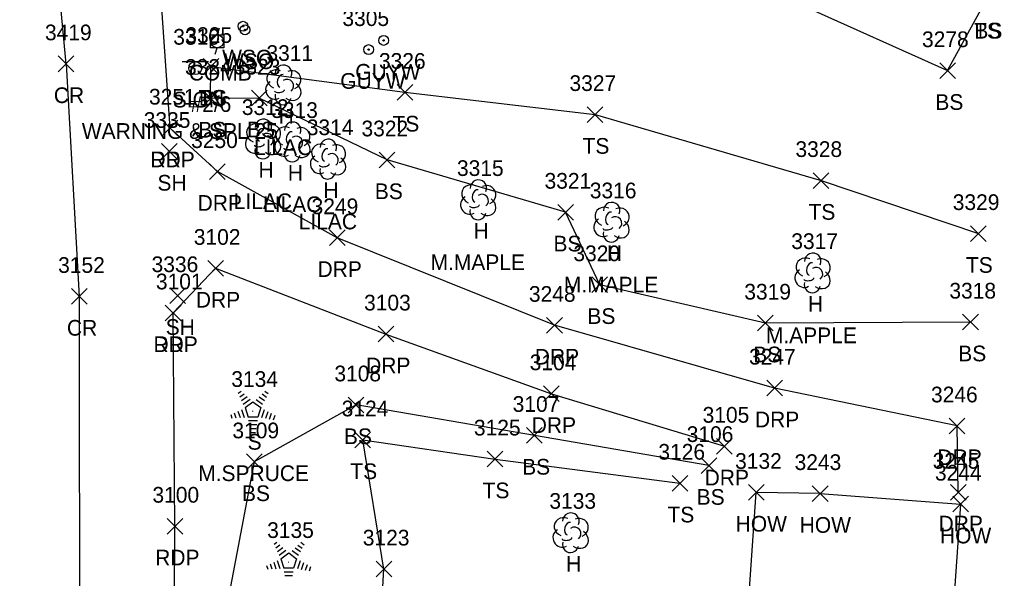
# Model space of a CAD drawing. Extents: x 1609623 to 1616187, y 756677 to 762826.
# Drawn here: x 1610609.3 to 1610734.4, y 762411.9 to 762483.1 of the extents above; entities that cross this region are included whole.
import ezdxf

# ---------------------------------------------------------------- set-up
doc = ezdxf.new("R2010")
doc.units = 0
for name, color, linetype in [('L_A', 7, 'Continuous'), ('L_C', 7, 'Continuous'), ('L_I', 7, 'Continuous'), ('L_TIC', 7, 'Continuous'), ('LBC', 7, 'Continuous'), ('LELB', 7, 'Continuous'), ('LTC', 7, 'Continuous'), ('LTD', 7, 'Continuous'), ('P_A', 7, 'Continuous'), ('P_I', 7, 'Continuous'), ('P_TIC', 7, 'Continuous'), ('PET', 7, 'Continuous'), ('PRC', 7, 'Continuous'), ('R_A', 7, 'Continuous'), ('R_I', 7, 'Continuous'), ('R_TIC', 7, 'Continuous'), ('RDP', 7, 'Continuous'), ('S_A', 7, 'Continuous'), ('S_C', 7, 'Continuous'), ('S_I', 7, 'Continuous'), ('SSGN', 7, 'Continuous'), ('U_A', 7, 'Continuous'), ('U_C', 7, 'Continuous'), ('U_I', 7, 'Continuous'), ('UP', 7, 'Continuous'), ('UPGW', 7, 'Continuous'), ('UWV', 7, 'Continuous')]:
    doc.layers.add(name, color=color, linetype=linetype)

msp = doc.modelspace()

# ---------------------------------------------------------------- linework, layer by layer
at = {"layer": 'L_TIC'}
for points in [[(1610632.67, 762476.12), (1610634.67, 762478.12)], [(1610634.67, 762476.12), (1610632.67, 762478.12)], [(1610632.67, 762476.12), (1610634.67, 762478.12)], [(1610634.67, 762476.12), (1610632.67, 762478.12)], [(1610726.55, 762475.59), (1610728.55, 762477.59)], [(1610728.55, 762475.59), (1610726.55, 762477.59)], [(1610657.39, 762472.83), (1610659.39, 762474.83)], [(1610659.39, 762472.83), (1610657.39, 762474.83)], [(1610632.62, 762472.06), (1610634.62, 762474.06)], [(1610634.62, 762472.06), (1610632.62, 762474.06)], [(1610638.83, 762472.09), (1610640.83, 762474.09)], [(1610640.83, 762472.09), (1610638.83, 762474.09)], [(1610681.62, 762470), (1610683.62, 762472)], [(1610683.62, 762470), (1610681.62, 762472)], [(1610627.36, 762465.3), (1610629.36, 762467.3)], [(1610629.36, 762465.3), (1610627.36, 762467.3)], [(1610655.11, 762464.22), (1610657.11, 762466.22)], [(1610657.11, 762464.22), (1610655.11, 762466.22)], [(1610710.42, 762461.59), (1610712.42, 762463.59)], [(1610712.42, 762461.59), (1610710.42, 762463.59)], [(1610677.87, 762457.55), (1610679.87, 762459.55)], [(1610679.87, 762457.55), (1610677.87, 762459.55)], [(1610730.48, 762454.83), (1610732.48, 762456.83)], [(1610732.48, 762454.83), (1610730.48, 762456.83)], [(1610682.21, 762448.31), (1610684.21, 762450.31)], [(1610684.21, 762448.31), (1610682.21, 762450.31)], [(1610628.42, 762446.92), (1610630.42, 762448.92)], [(1610630.42, 762446.92), (1610628.42, 762448.92)], [(1610729.47, 762443.55), (1610731.47, 762445.55)], [(1610731.47, 762443.55), (1610729.47, 762445.55)], [(1610703.34, 762443.42), (1610705.34, 762445.42)], [(1610705.34, 762443.42), (1610703.34, 762445.42)], [(1610651.17, 762433), (1610653.17, 762435)], [(1610653.17, 762433), (1610651.17, 762435)], [(1610652.02, 762428.54), (1610654.02, 762430.54)], [(1610654.02, 762428.54), (1610652.02, 762430.54)], [(1610673.89, 762429.11), (1610675.89, 762431.11)], [(1610675.89, 762429.11), (1610673.89, 762431.11)], [(1610668.88, 762426.1), (1610670.88, 762428.1)], [(1610670.88, 762426.1), (1610668.88, 762428.1)], [(1610638.18, 762425.74), (1610640.18, 762427.74)], [(1610640.18, 762425.74), (1610638.18, 762427.74)], [(1610696.13, 762425.27), (1610698.13, 762427.27)], [(1610698.13, 762425.27), (1610696.13, 762427.27)], [(1610692.44, 762423.02), (1610694.44, 762425.02)], [(1610694.44, 762423.02), (1610692.44, 762425.02)], [(1610702.16, 762421.85), (1610704.16, 762423.85)], [(1610704.16, 762421.85), (1610702.16, 762423.85)], [(1610710.31, 762421.7), (1610712.31, 762423.7)], [(1610712.31, 762421.7), (1610710.31, 762423.7)], [(1610728.2, 762420.35), (1610730.2, 762422.35)], [(1610730.2, 762420.35), (1610728.2, 762422.35)], [(1610654.72, 762412.08), (1610656.72, 762414.08)], [(1610656.72, 762412.08), (1610654.72, 762414.08)]]:
    msp.add_lwpolyline(points, dxfattribs=at)
at = {"layer": 'LBC'}
for points in [[(1610726.11, 762376.75), (1610699.95, 762378.87), (1610701.66, 762401.3), (1610703.16, 762422.85)], [(1610711.31, 762422.7), (1610703.16, 762422.85)], [(1610711.31, 762422.7), (1610729.2, 762421.35)], [(1610729.2, 762421.35), (1610726.11, 762376.75)]]:
    msp.add_lwpolyline(points, dxfattribs=at)
at = {"layer": 'LELB'}
for points in [[(1610617.17, 762584.2), (1610624.48, 762566.64), (1610633.74, 762545.52), (1610644.17, 762527.74), (1610665.38, 762506.98), (1610690.4, 762493.29), (1610727.55, 762476.59), (1610732.52, 762485.68)], [(1610730.47, 762444.55), (1610704.34, 762444.42), (1610683.21, 762449.31), (1610678.87, 762458.55), (1610656.11, 762465.22), (1610639.83, 762473.09), (1610633.62, 762473.06), (1610633.67, 762477.12)], [(1610633.67, 762477.12), (1610658.39, 762473.83), (1610682.62, 762471), (1610711.42, 762462.59), (1610731.48, 762455.83)], [(1610697.13, 762426.27), (1610674.89, 762430.11), (1610652.17, 762434), (1610639.18, 762426.74), (1610634.28, 762401.02), (1610634.83, 762377.24), (1610647.78, 762368.68), (1610668.95, 762368.97), (1610685.96, 762365.63), (1610692.89, 762346.49), (1610722.2, 762344.28)], [(1610722.2, 762344.28), (1610724.11, 762366.05), (1610703.11, 762368.06), (1610688.81, 762373.62), (1610671.14, 762377.72), (1610655.71, 762382.19), (1610654.46, 762391.1), (1610655.72, 762413.08), (1610653.02, 762429.54), (1610669.88, 762427.1), (1610693.44, 762424.02)]]:
    msp.add_lwpolyline(points, dxfattribs=at)
at = {"layer": 'LTC'}
for p, q in [((1610637.15, 762435.5), (1610637.51, 762435.76)), ((1610640.55, 762435.74), (1610640.97, 762435.43)), ((1610637.36, 762435.03), (1610637.89, 762435.42)), ((1610637.57, 762434.57), (1610638.28, 762435.08)), ((1610637.78, 762434.1), (1610638.66, 762434.74)), ((1610638.01, 762433.65), (1610639.02, 762434.38)), ((1610639.02, 762434.38), (1610640.02, 762433.66)), ((1610639.44, 762434.69), (1610640.25, 762434.1)), ((1610639.81, 762435.04), (1610640.49, 762434.55)), ((1610640.18, 762435.39), (1610640.73, 762434.99)), ((1610637.1, 762433.21), (1610637.37, 762432.38)), ((1610637.55, 762433.43), (1610637.88, 762432.41)), ((1610638.01, 762433.65), (1610638.39, 762432.45)), ((1610640.02, 762433.66), (1610639.62, 762432.45)), ((1610640.45, 762433.38), (1610640.11, 762432.35)), ((1610640.9, 762433.13), (1610640.61, 762432.25)), ((1610636.19, 762432.78), (1610636.34, 762432.31)), ((1610636.64, 762432.99), (1610636.85, 762432.34)), ((1610639.62, 762432.45), (1610638.39, 762432.45)), ((1610639.59, 762431.95), (1610638.44, 762431.95)), ((1610641.34, 762432.88), (1610641.1, 762432.15)), ((1610641.79, 762432.63), (1610641.6, 762432.06)), ((1610639.5, 762431.45), (1610638.51, 762431.45)), ((1610639.42, 762430.95), (1610638.59, 762430.95)), ((1610639.33, 762430.45), (1610638.66, 762430.45)), ((1610641.72, 762416.25), (1610642.08, 762416.5)), ((1610641.93, 762415.78), (1610642.46, 762416.17)), ((1610642.14, 762415.32), (1610642.84, 762415.83)), ((1610644.38, 762415.79), (1610645.06, 762415.3)), ((1610644.75, 762416.14), (1610645.3, 762415.74)), ((1610645.12, 762416.49), (1610645.54, 762416.18)), ((1610642.35, 762414.85), (1610643.23, 762415.49)), ((1610642.57, 762414.39), (1610643.59, 762415.13)), ((1610642.57, 762414.39), (1610642.96, 762413.2)), ((1610643.59, 762415.13), (1610644.58, 762414.4)), ((1610644.01, 762415.44), (1610644.82, 762414.85)), ((1610644.58, 762414.4), (1610644.19, 762413.2)), ((1610640.75, 762413.53), (1610640.91, 762413.06)), ((1610641.21, 762413.74), (1610641.42, 762413.09)), ((1610641.66, 762413.96), (1610641.94, 762413.12)), ((1610642.12, 762414.18), (1610642.45, 762413.16)), ((1610644.19, 762413.2), (1610642.96, 762413.2)), ((1610645.02, 762414.13), (1610644.68, 762413.09)), ((1610645.46, 762413.88), (1610645.18, 762413)), ((1610645.91, 762413.63), (1610645.67, 762412.9)), ((1610646.35, 762413.38), (1610646.17, 762412.81)), ((1610644.15, 762412.7), (1610643.01, 762412.7)), ((1610644.07, 762412.2), (1610643.08, 762412.2))]:
    msp.add_line(p, q, dxfattribs=at)
at = {"layer": 'LTD'}
for p, q in [((1610642.87, 762474.83), (1610642.87, 762474.83)), ((1610642.87, 762474.83), (1610642.87, 762474.83)), ((1610640.29, 762467.94), (1610640.29, 762467.94)), ((1610640.29, 762467.94), (1610640.29, 762467.94)), ((1610644.03, 762467.56), (1610644.03, 762467.56)), ((1610644.03, 762467.56), (1610644.03, 762467.56)), ((1610648.57, 762465.37), (1610648.57, 762465.37)), ((1610648.57, 762465.37), (1610648.57, 762465.37)), ((1610667.71, 762460.17), (1610667.71, 762460.17)), ((1610667.71, 762460.17), (1610667.71, 762460.17)), ((1610684.7, 762457.32), (1610684.7, 762457.32)), ((1610684.7, 762457.32), (1610684.7, 762457.32)), ((1610710.32, 762450.86), (1610710.32, 762450.86)), ((1610710.32, 762450.86), (1610710.32, 762450.86)), ((1610679.5, 762417.76), (1610679.5, 762417.76)), ((1610679.5, 762417.76), (1610679.5, 762417.76))]:
    msp.add_line(p, q, dxfattribs=at)
for centre in [(1610642.92, 762476.26), (1610640.34, 762469.37), (1610644.08, 762469), (1610648.62, 762466.81), (1610667.76, 762461.61), (1610684.75, 762458.76), (1610710.37, 762452.29), (1610679.54, 762419.19)]:
    msp.add_arc(centre, 1.05, 335.5272, 180.9563, dxfattribs=at)
for centre, major_axis, ratio, start_param, end_param in [((1610642.08, 762475.5), (1.21, -0.51), 0.895232, 1.570796, 4.712389), ((1610642.66, 762475.29), (-0.208, -0.792), 0.645439, 3.141593, 6.283185), ((1610643.37, 762474.66), (-0.5, 0.667), 0.989748, 3.141593, 6.283185), ((1610643.91, 762475.41), (-1.14, -0.48), 0.949671, 1.570796, 4.712389), ((1610641.79, 762474.12), (0.58, -1.04), 0.959034, 3.141593, 6.283185), ((1610643.87, 762474), (-1.09, 0.79), 0.841452, 1.570796, 4.712389), ((1610642.87, 762473.33), (0.26, 1.06), 0.942809, 1.570796, 4.712389), ((1610642.41, 762474.08), (-0.625, -0.083), 0.423636, 0, 3.141593), ((1610639.5, 762468.6), (1.21, -0.51), 0.895232, 1.570796, 4.712389), ((1610641.33, 762468.52), (-1.14, -0.48), 0.949671, 1.570796, 4.712389), ((1610643.24, 762468.23), (1.21, -0.51), 0.895232, 1.570796, 4.712389), ((1610645.07, 762468.15), (-1.14, -0.48), 0.949671, 1.570796, 4.712389), ((1610639.21, 762467.23), (0.58, -1.04), 0.959034, 3.141593, 6.283185), ((1610640.08, 762468.39), (-0.208, -0.792), 0.645439, 3.141593, 6.283185), ((1610640.79, 762467.77), (-0.5, 0.667), 0.989748, 3.141593, 6.283185), ((1610643.82, 762468.02), (-0.208, -0.792), 0.645439, 3.141593, 6.283185), ((1610644.53, 762467.4), (-0.5, 0.667), 0.989748, 3.141593, 6.283185), ((1610639.83, 762467.18), (-0.625, -0.083), 0.423636, 0, 3.141593), ((1610641.29, 762467.1), (-1.09, 0.79), 0.841452, 1.570796, 4.712389), ((1610642.95, 762466.86), (0.58, -1.04), 0.959034, 3.141593, 6.283185), ((1610643.57, 762466.81), (-0.625, -0.083), 0.423636, 0, 3.141593), ((1610645.03, 762466.73), (-1.09, 0.79), 0.841452, 1.570796, 4.712389), ((1610647.78, 762466.04), (1.21, -0.51), 0.895232, 1.570796, 4.712389), ((1610649.61, 762465.95), (-1.14, -0.48), 0.949671, 1.570796, 4.712389), ((1610640.29, 762466.44), (0.26, 1.06), 0.942809, 1.570796, 4.712389), ((1610644.03, 762466.06), (0.26, 1.06), 0.942809, 1.570796, 4.712389), ((1610647.49, 762464.66), (0.58, -1.04), 0.959034, 3.141593, 6.283185), ((1610648.36, 762465.83), (-0.208, -0.792), 0.645439, 3.141593, 6.283185), ((1610649.07, 762465.2), (-0.5, 0.667), 0.989748, 3.141593, 6.283185), ((1610648.11, 762464.62), (-0.625, -0.083), 0.423636, 0, 3.141593), ((1610649.57, 762464.54), (-1.09, 0.79), 0.841452, 1.570796, 4.712389), ((1610648.57, 762463.87), (0.26, 1.06), 0.942809, 1.570796, 4.712389), ((1610666.92, 762460.84), (1.21, -0.51), 0.895232, 1.570796, 4.712389), ((1610668.75, 762460.76), (-1.14, -0.48), 0.949671, 1.570796, 4.712389), ((1610667.5, 762460.63), (-0.208, -0.792), 0.645439, 3.141593, 6.283185), ((1610668.21, 762460.01), (-0.5, 0.667), 0.989748, 3.141593, 6.283185), ((1610666.63, 762459.46), (0.58, -1.04), 0.959034, 3.141593, 6.283185), ((1610667.25, 762459.42), (-0.625, -0.083), 0.423636, 0, 3.141593), ((1610668.71, 762459.34), (-1.09, 0.79), 0.841452, 1.570796, 4.712389), ((1610683.91, 762457.99), (1.21, -0.51), 0.895232, 1.570796, 4.712389), ((1610667.71, 762458.67), (0.26, 1.06), 0.942809, 1.570796, 4.712389), ((1610684.49, 762457.78), (-0.208, -0.792), 0.645439, 3.141593, 6.283185), ((1610685.2, 762457.15), (-0.5, 0.667), 0.989748, 3.141593, 6.283185), ((1610685.74, 762457.9), (-1.14, -0.48), 0.949671, 1.570796, 4.712389), ((1610683.62, 762456.61), (0.58, -1.04), 0.959034, 3.141593, 6.283185), ((1610685.7, 762456.49), (-1.09, 0.79), 0.841452, 1.570796, 4.712389), ((1610684.7, 762455.82), (0.26, 1.06), 0.942809, 1.570796, 4.712389), ((1610684.24, 762456.57), (-0.625, -0.083), 0.423636, 0, 3.141593), ((1610709.53, 762451.52), (1.21, -0.51), 0.895232, 1.570796, 4.712389), ((1610710.12, 762451.31), (-0.208, -0.792), 0.645439, 3.141593, 6.283185), ((1610711.37, 762451.44), (-1.14, -0.48), 0.949671, 1.570796, 4.712389), ((1610709.24, 762450.15), (0.58, -1.04), 0.959034, 3.141593, 6.283185), ((1610710.82, 762450.69), (-0.5, 0.667), 0.989748, 3.141593, 6.283185), ((1610711.32, 762450.02), (-1.09, 0.79), 0.841452, 1.570796, 4.712389), ((1610710.32, 762449.36), (0.26, 1.06), 0.942809, 1.570796, 4.712389), ((1610709.87, 762450.1), (-0.625, -0.083), 0.423636, 0, 3.141593), ((1610678.7, 762418.43), (1.21, -0.51), 0.895232, 1.570796, 4.712389), ((1610680.54, 762418.34), (-1.14, -0.48), 0.949671, 1.570796, 4.712389), ((1610678.41, 762417.05), (0.58, -1.04), 0.959034, 3.141593, 6.283185), ((1610679.29, 762418.22), (-0.208, -0.792), 0.645439, 3.141593, 6.283185), ((1610680, 762417.59), (-0.5, 0.667), 0.989748, 3.141593, 6.283185), ((1610679.04, 762417.01), (-0.625, -0.083), 0.423636, 0, 3.141593), ((1610680.5, 762416.93), (-1.09, 0.79), 0.841452, 1.570796, 4.712389), ((1610679.5, 762416.26), (0.26, 1.06), 0.942809, 1.570796, 4.712389)]:
    msp.add_ellipse(centre, major_axis=major_axis, ratio=ratio, start_param=start_param, end_param=end_param, dxfattribs=at)
at = {"layer": 'P_TIC'}
for points in [[(1610614.21, 762476.46), (1610616.21, 762478.46)], [(1610616.21, 762476.46), (1610614.21, 762478.46)], [(1610627.46, 762468.27), (1610629.46, 762470.27)], [(1610629.46, 762468.27), (1610627.46, 762470.27)], [(1610615.88, 762446.82), (1610617.88, 762448.82)], [(1610617.88, 762446.82), (1610615.88, 762448.82)], [(1610627.85, 762444.72), (1610629.85, 762446.72)], [(1610629.85, 762444.72), (1610627.85, 762446.72)], [(1610628.07, 762417.54), (1610630.07, 762419.54)], [(1610630.07, 762417.54), (1610628.07, 762419.54)]]:
    msp.add_lwpolyline(points, dxfattribs=at)
at = {"layer": 'PET'}
for points in [[(1610628.46, 762469.27), (1610626.5, 762497.43), (1610623.85, 762542.71), (1610615.75, 762574.17), (1610605.76, 762602.47), (1610594.8, 762629.34)], [(1610628.08, 762347.79), (1610628.95, 762388.2), (1610629.07, 762418.54), (1610628.85, 762445.72)]]:
    msp.add_lwpolyline(points, dxfattribs=at)
at = {"layer": 'PRC'}
for points in [[(1610615.21, 762477.46), (1610610.95, 762522.65), (1610602.63, 762567.01), (1610590.24, 762605.14), (1610573.67, 762636.29), (1610563.51, 762651.45)], [(1610615.21, 762477.46), (1610616.88, 762447.82)], [(1610616.88, 762447.82), (1610616.9, 762397.77), (1610615.76, 762350.31), (1610614.29, 762312.68), (1610612.91, 762268.6), (1610611.57, 762220.08)]]:
    msp.add_lwpolyline(points, dxfattribs=at)
at = {"layer": 'R_TIC'}
for points in [[(1610627.46, 762468.27), (1610629.46, 762470.27)], [(1610629.46, 762468.27), (1610627.46, 762470.27)], [(1610633.48, 762462.73), (1610635.48, 762464.73)], [(1610635.48, 762462.73), (1610633.48, 762464.73)], [(1610648.76, 762454.3), (1610650.76, 762456.3)], [(1610650.76, 762454.3), (1610648.76, 762456.3)], [(1610633.25, 762450.4), (1610635.25, 762452.4)], [(1610635.25, 762450.4), (1610633.25, 762452.4)], [(1610627.85, 762444.72), (1610629.85, 762446.72)], [(1610629.85, 762444.72), (1610627.85, 762446.72)], [(1610676.45, 762443.14), (1610678.45, 762445.14)], [(1610678.45, 762443.14), (1610676.45, 762445.14)], [(1610654.96, 762442.03), (1610656.96, 762444.03)], [(1610656.96, 762442.03), (1610654.96, 762444.03)], [(1610704.51, 762435.14), (1610706.51, 762437.14)], [(1610706.51, 762435.14), (1610704.51, 762437.14)], [(1610676.06, 762434.42), (1610678.06, 762436.42)], [(1610678.06, 762434.42), (1610676.06, 762436.42)], [(1610727.76, 762430.32), (1610729.76, 762432.32)], [(1610729.76, 762430.32), (1610727.76, 762432.32)], [(1610698.1, 762427.73), (1610700.1, 762429.73)], [(1610700.1, 762427.73), (1610698.1, 762429.73)], [(1610727.91, 762421.87), (1610729.91, 762423.87)], [(1610729.91, 762421.87), (1610727.91, 762423.87)]]:
    msp.add_lwpolyline(points, dxfattribs=at)
at = {"layer": 'RDP'}
for points in [[(1610728.91, 762422.87), (1610728.76, 762431.32), (1610705.51, 762436.14), (1610677.45, 762444.14), (1610649.76, 762455.3), (1610634.48, 762463.73), (1610628.46, 762469.27)], [(1610628.85, 762445.72), (1610634.25, 762451.4), (1610655.96, 762443.03), (1610677.06, 762435.42), (1610699.1, 762428.73)]]:
    msp.add_lwpolyline(points, dxfattribs=at)
at = {"layer": 'SSGN'}
for p, q in [((1610630.01, 762477.75), (1610633.35, 762477.75)), ((1610631.66, 762476.92), (1610631.66, 762476.92))]:
    msp.add_line(p, q, dxfattribs=at)
msp.add_circle((1610631.66, 762476.92), 0.833, dxfattribs=at)
at = {"layer": 'UP'}
for p, q in [((1610634.7, 762482), (1610634.45, 762481.17)), ((1610633.62, 762479.5), (1610633.62, 762481.17)), ((1610633.62, 762481.17), (1610635.29, 762481.17)), ((1610635.29, 762481.17), (1610635.29, 762479.5)), ((1610635.29, 762479.5), (1610633.62, 762479.5)), ((1610634.2, 762478.67), (1610634.45, 762479.5)), ((1610634.45, 762480.33), (1610634.45, 762480.33))]:
    msp.add_line(p, q, dxfattribs=at)
msp.add_circle((1610634.45, 762480.33), 0.833, dxfattribs=at)
at = {"layer": 'UPGW'}
for centre, radius in [((1610655.67, 762480.44), 0.625), ((1610653.76, 762479.28), 0.625), ((1610653.76, 762479.28), 0.0833), ((1610655.67, 762480.44), 0.0833)]:
    msp.add_circle(centre, radius, dxfattribs=at)
at = {"layer": 'UWV'}
for centre, radius in [((1610637.76, 762482.25), 0.625), ((1610638.01, 762481.79), 0.625), ((1610637.76, 762482.25), 0.0833), ((1610638.01, 762481.79), 0.0833)]:
    msp.add_circle(centre, radius, dxfattribs=at)

# ---------------------------------------------------------------- texts
at = {"layer": 'L_A'}
for s, p in [('TS', (1610730.93, 762480.68)), ('BS', (1610730.96, 762480.68)), ('TS', (1610632.08, 762472.12)), ('BS', (1610632.12, 762472.12)), ('BS', (1610725.99, 762471.59)), ('H', (1610642.3, 762469.83)), ('TS', (1610656.8, 762468.83)), ('BS', (1610632.06, 762468.06)), ('BS', (1610638.27, 762468.09)), ('TS', (1610681.03, 762466)), ('H', (1610639.72, 762462.94)), ('H', (1610643.46, 762462.56)), ('SH', (1610626.85, 762461.3)), ('H', (1610648, 762460.37)), ('BS', (1610654.55, 762460.22)), ('TS', (1610709.83, 762457.59)), ('H', (1610667.14, 762455.17)), ('BS', (1610677.32, 762453.55)), ('H', (1610684.13, 762452.32)), ('TS', (1610729.89, 762450.83)), ('H', (1610709.76, 762445.86)), ('BS', (1610681.65, 762444.31)), ('SH', (1610627.9, 762442.92)), ('BS', (1610702.78, 762439.42)), ('BS', (1610728.91, 762439.55)), ('BS', (1610650.61, 762429)), ('S', (1610638.34, 762428.29)), ('BS', (1610673.33, 762425.11)), ('TS', (1610651.43, 762424.54)), ('BS', (1610637.62, 762421.74)), ('TS', (1610668.29, 762422.1)), ('BS', (1610695.57, 762421.27)), ('TS', (1610691.85, 762419.02)), ('HOW', (1610700.54, 762417.85)), ('HOW', (1610708.7, 762417.7)), ('HOW', (1610726.58, 762416.35)), ('H', (1610678.93, 762412.76))]:
    msp.add_text(s, height=2, dxfattribs=at).set_placement(p)
at = {"layer": 'L_C'}
for s, p in [('LILAC', (1610639.14, 762465.83)), ('LILAC', (1610636.57, 762458.94)), ('LILAC', (1610640.31, 762458.56)), ('LILAC', (1610644.85, 762456.37)), ('M.MAPLE', (1610661.65, 762451.17)), ('M.MAPLE', (1610678.64, 762448.32)), ('M.APPLE', (1610704.39, 762441.86)), ('M.SPRUCE', (1610632.04, 762424.29))]:
    msp.add_text(s, height=2, dxfattribs=at).set_placement(p)
at = {"layer": 'L_I'}
for s, p in [('3325', (1610630.41, 762480.12)), ('3325', (1610630.41, 762480.12)), ('3278', (1610724.29, 762479.59)), ('3311', (1610640.74, 762477.83)), ('3324', (1610630.36, 762476.06)), ('3323', (1610636.57, 762476.09)), ('3326', (1610655.08, 762476.83)), ('3327', (1610679.36, 762474)), ('3312', (1610637.6, 762470.94)), ('3313', (1610641.34, 762470.56)), ('3335', (1610625.1, 762469.3)), ('3314', (1610645.88, 762468.37)), ('3322', (1610652.85, 762468.22)), ('3328', (1610708.16, 762465.59)), ('3315', (1610665.02, 762463.17)), ('3321', (1610676.18, 762461.55)), ('3316', (1610681.95, 762460.32)), ('3329', (1610728.21, 762458.83)), ('3317', (1610707.63, 762453.86)), ('3320', (1610679.86, 762452.31)), ('3336', (1610626.1, 762450.92)), ('3319', (1610701.64, 762447.42)), ('3318', (1610727.78, 762447.55)), ('3134', (1610636.26, 762436.29)), ('3108', (1610649.4, 762437)), ('3124', (1610650.33, 762432.54)), ('3107', (1610672.12, 762433.11)), ('3109', (1610636.4, 762429.74)), ('3125', (1610667.18, 762430.1)), ('3106', (1610694.3, 762429.27)), ('3126', (1610690.69, 762427.02)), ('3132', (1610700.47, 762425.85)), ('3243', (1610708.05, 762425.7)), ('3244', (1610725.94, 762424.35)), ('3133', (1610676.8, 762420.76)), ('3135', (1610640.83, 762417.04)), ('3123', (1610653.02, 762416.08))]:
    msp.add_text(s, height=2, dxfattribs=at).set_placement(p)
at = {"layer": 'LTC'}
for p in [(1610638.9, 762433.39), (1610643.47, 762414.14)]:
    msp.add_text('.', height=1.04, rotation=270, dxfattribs=at).set_placement(p)
at = {"layer": 'P_A'}
for s, p in [('CR', (1610613.64, 762472.46)), ('RDP', (1610625.95, 762464.27)), ('CR', (1610615.31, 762442.82)), ('RDP', (1610626.34, 762440.72)), ('RDP', (1610626.56, 762413.54))]:
    msp.add_text(s, height=2, dxfattribs=at).set_placement(p)
at = {"layer": 'P_I'}
for s, p in [('3419', (1610612.51, 762480.46)), ('3251', (1610625.77, 762472.27)), ('3152', (1610614.19, 762450.82)), ('3101', (1610626.65, 762448.72)), ('3100', (1610626.21, 762421.54))]:
    msp.add_text(s, height=2, dxfattribs=at).set_placement(p)
at = {"layer": 'R_A'}
for p in [(1610625.95, 762464.27), (1610631.97, 762458.73), (1610647.25, 762450.3), (1610631.74, 762446.4), (1610626.34, 762440.72), (1610674.94, 762439.14), (1610653.44, 762438.03), (1610703, 762431.14), (1610674.55, 762430.42), (1610726.25, 762426.32), (1610696.59, 762423.73), (1610726.4, 762417.87)]:
    msp.add_text('DRP', height=2, dxfattribs=at).set_placement(p)
at = {"layer": 'R_I'}
for s, p in [('3251', (1610625.77, 762472.27)), ('3250', (1610631.14, 762466.73)), ('3249', (1610646.49, 762458.3)), ('3102', (1610631.48, 762454.4)), ('3101', (1610626.65, 762448.72)), ('3103', (1610653.18, 762446.03)), ('3248', (1610674.19, 762447.14)), ('3247', (1610702.25, 762439.14)), ('3104', (1610674.29, 762438.42)), ('3246', (1610725.44, 762434.32)), ('3105', (1610696.33, 762431.73)), ('3245', (1610725.65, 762425.87))]:
    msp.add_text(s, height=2, dxfattribs=at).set_placement(p)
at = {"layer": 'S_A'}
msp.add_text('SIGN', height=2, dxfattribs=at).set_placement((1610628.8, 762471.9))
at = {"layer": 'S_C'}
msp.add_text('WARNING & SPL 25', height=2, dxfattribs=at).set_placement((1610617.21, 762467.9))
at = {"layer": 'S_I'}
msp.add_text('3310', height=2, dxfattribs=at).set_placement((1610628.86, 762479.9))
at = {"layer": 'U_A'}
for s, p in [('WSO', (1610635.09, 762477.25)), ('WSO', (1610635.34, 762476.79)), ('COMB', (1610630.84, 762475.33)), ('GUYW', (1610652.06, 762475.44)), ('GUYW', (1610650.15, 762474.28))]:
    msp.add_text(s, height=2, dxfattribs=at).set_placement(p)
at = {"layer": 'U_C'}
msp.add_text('#2/6', height=2, dxfattribs=at).set_placement((1610631.06, 762471.33))
at = {"layer": 'U_I'}
msp.add_text('3305', height=2, dxfattribs=at).set_placement((1610650.42, 762482.28))

doc.saveas('drawing.dxf')
